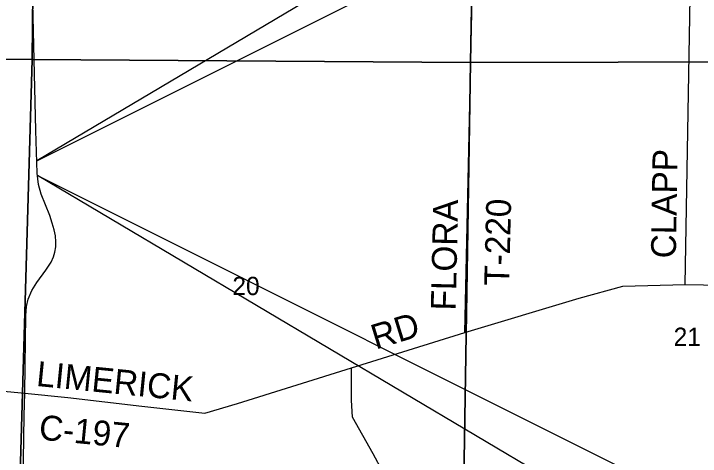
# Model space of a CAD drawing. Extents: x 0 to 34, y 0 to 22.
# Drawn here: x 26.932 to 28.499, y 16.014 to 17.024 of the extents above; entities that cross this region are included whole.
import ezdxf

# ---------------------------------------------------------------- set-up
doc = ezdxf.new("R2010")
doc.units = 0
for name, color, linetype in [('GM_X_County_Road', 7, 'Continuous'), ('GM_X_County_Road_Text', 7, 'Continuous'), ('GM_X_Section', 7, 'Continuous'), ('GM_X_Section_Text', 7, 'Continuous'), ('GM_X_State_Route', 7, 'Continuous'), ('GM_X_Township_Road', 7, 'Continuous'), ('GM_X_Township_Road_Text', 7, 'Continuous'), ('SH_Data', 7, 'Continuous')]:
    doc.layers.add(name, color=color, linetype=linetype)

msp = doc.modelspace()

# ---------------------------------------------------------------- linework, layer by layer
at = {"layer": 'GM_X_County_Road'}
for points in [[(26.566, 16.4258), (26.5747, 16.3759), (26.5835, 16.236), (26.5843, 16.2185), (26.585, 16.2101), (26.5874, 16.1995), (26.5882, 16.1976), (26.5926, 16.191), (26.5963, 16.1882), (26.6013, 16.1852), (26.6092, 16.1839), (26.867, 16.1627), (26.9001, 16.1639), (26.9576, 16.1588)], [(26.9576, 16.1588), (27.0552, 16.1482), (27.2245, 16.1284), (27.3685, 16.1128), (27.4425, 16.1348), (27.7027, 16.2161), (27.9618, 16.2967), (28.2223, 16.3749), (28.3222, 16.4022), (28.4643, 16.4064), (28.7151, 16.4016), (28.9616, 16.4068)]]:
    msp.add_lwpolyline(points, dxfattribs=at)
at = {"layer": 'GM_X_Section'}
for points in [[(26.984, 17.9172), (26.974, 16.9197), (25.9875, 16.9239), (26.0158, 17.891), (26.0171, 17.9156)], [(27.9928, 17.9132), (27.9749, 16.9131), (26.974, 16.9197), (26.984, 17.9172)], [(26.974, 16.9197), (26.945, 15.9224), (25.9635, 15.9304), (25.9861, 16.8906), (25.9875, 16.9239)], [(27.9749, 16.9131), (27.9584, 15.9108), (26.945, 15.9224), (26.974, 16.9197)]]:
    msp.add_lwpolyline(points, close=True, dxfattribs=at)
for points in [[(28.9884, 17.4387), (28.9846, 16.9148), (27.9749, 16.9131), (27.9928, 17.9132), (28.4862, 17.9139)], [(28.4862, 15.9049), (27.9584, 15.9108), (27.9749, 16.9131), (28.9846, 16.9148), (28.9715, 15.9053)]]:
    msp.add_lwpolyline(points, dxfattribs=at)
at = {"layer": 'GM_X_State_Route'}
msp.add_lwpolyline([(26.9497, 15.6998), (26.956, 16.1074), (26.9576, 16.1588), (26.9582, 16.2198), (26.9595, 16.3358), (26.9608, 16.356), (26.9649, 16.373), (26.9732, 16.3927), (26.9851, 16.4107), (27.0055, 16.4391), (27.0171, 16.4574), (27.023, 16.4695), (27.0261, 16.48), (27.0278, 16.4919), (27.0283, 16.5038), (27.0271, 16.5177), (27.0242, 16.531), (27.0198, 16.5463), (27.0142, 16.5636), (26.9945, 16.6122), (26.9887, 16.6341), (26.9855, 16.6606), (26.9826, 16.7575), (26.9729, 17.1786)], dxfattribs=at)
at = {"layer": 'GM_X_Township_Road'}
for p, q in [((27.9618, 16.2967), (27.9854, 17.4096)), ((28.4643, 16.4064), (28.4819, 17.4065))]:
    msp.add_line(p, q, dxfattribs=at)
msp.add_lwpolyline([(28.4862, 15.6748), (28.3257, 15.7191), (28.2426, 15.7489), (28.2094, 15.7567), (28.0091, 15.7671), (27.8954, 15.8533), (27.7969, 15.9377), (27.7527, 16.0204), (27.7055, 16.1036), (27.703, 16.1424), (27.7027, 16.2161)], dxfattribs=at)
at = {"layer": 'SH_Data'}
for points in [[(28.4862, 17.5787), (26.9847, 16.6887), (28.4862, 17.4387)], [(26.9862, 16.6553), (28.4862, 15.9053), (28.4862, 15.7653)]]:
    msp.add_lwpolyline(points, close=True, dxfattribs=at)

# ---------------------------------------------------------------- texts
at = {"layer": 'GM_X_County_Road_Text'}
for s, rotation, p in [('RD', 17.1766, (27.7583, 16.2575)), ('LIMERICK', 354.3034, (26.982, 16.1751)), ('C-197', 354.4817, (26.9879, 16.0529))]:
    msp.add_text(s, height=0.05682, rotation=rotation, dxfattribs=at).set_placement(p)
at = {"layer": 'GM_X_Section_Text'}
for s, p in [('20', (27.4311, 16.382)), ('21', (28.4382, 16.2661))]:
    msp.add_text(s, height=0.04186, rotation=0, dxfattribs=at).set_placement(p)
at = {"layer": 'GM_X_Township_Road_Text'}
for s, rotation, p in [('CLAPP', 89.1157, (28.4433, 16.4657)), ('FLORA', 88.7408, (27.9408, 16.3466)), ('T-220', 88.5957, (28.0626, 16.4029))]:
    msp.add_text(s, height=0.05682, rotation=rotation, dxfattribs=at).set_placement(p)

doc.saveas('drawing.dxf')
